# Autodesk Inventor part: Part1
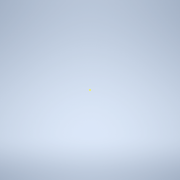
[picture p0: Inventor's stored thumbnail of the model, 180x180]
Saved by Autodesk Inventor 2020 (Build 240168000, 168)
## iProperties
Created: 2019-09
Part Number: Part1
Material: Generic
Document SubType Name: Modeling
Designer: Synergysoft
Density: 1 g/cm^3
Appearance: Default
Author: Synergysoft
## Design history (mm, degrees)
sketch "Sketch1"
  geometry: 1 further point
  constraints: 1 other
